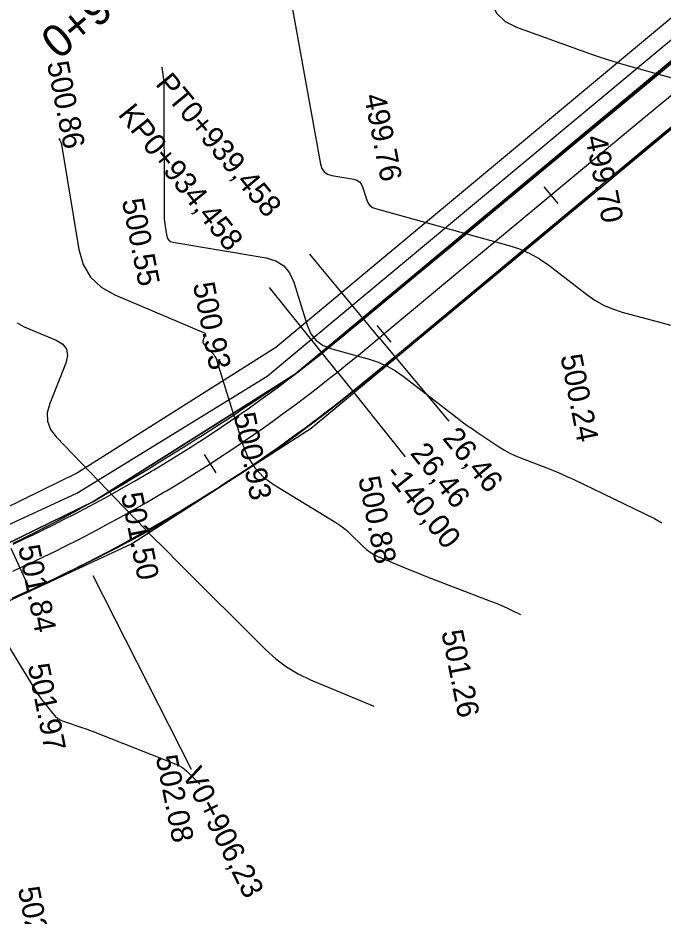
# Model space of a CAD drawing. Extents: x -636600 to -628587, y -1090963 to -1085869.
# Drawn here: x -629641.2 to -629581.8, y -1090525.3 to -1090442.6 of the extents above; entities that cross this region are included whole.
import ezdxf

# ---------------------------------------------------------------- set-up
doc = ezdxf.new("R2010")
doc.units = 0
for name, color, linetype in [('01_PARCELY_NÁVRH_PC', 7, 'Continuous'), ('06_ÚSES_IP_NAVRH', 7, 'Continuous'), ('Ex_Major Contours', 7, 'Continuous'), ('Ex_Minor Contours', 7, 'Continuous'), ('HEKTOMETRY100', 7, 'Continuous'), ('HEKTOMETRY20', 7, 'Continuous'), ('HL_BODY', 7, 'Continuous'), ('koty_vše', 7, 'Continuous'), ('POLOMERY', 7, 'Continuous'), ('situace_osa', 7, 'Continuous'), ('situace_těleso', 7, 'Continuous'), ('situace_vozovka', 7, 'Continuous'), ('VRCHOLY', 7, 'Continuous')]:
    doc.layers.add(name, color=color, linetype=linetype)

msp = doc.modelspace()

# ---------------------------------------------------------------- linework, layer by layer
at = {"layer": '01_PARCELY_NÁVRH_PC'}
for points in [[(-629847.268, -1090544.916), (-629662.104, -1090498.529), (-629646.495, -1090493.05), (-629634.26, -1090487.093), (-629615.686, -1090475.355), (-629557.933, -1090427.231), (-629554.65, -1090422.019), (-629539.331, -1090409.32), (-629533.536, -1090406.901), (-629497.762, -1090372.287), (-629488.059, -1090365.855), (-629480.703, -1090362.631), (-629491.445, -1090364.5), (-629499.65, -1090369.939), (-629535.214, -1090404.351), (-629617.455, -1090472.924), (-629635.723, -1090484.468), (-629647.652, -1090490.277), (-629662.967, -1090495.652), (-629847.268, -1090541.823)], [(-629497.762, -1090372.287), (-629533.536, -1090406.901), (-629539.331, -1090409.32), (-629554.65, -1090422.019), (-629557.933, -1090427.231), (-629615.686, -1090475.355), (-629634.26, -1090487.093), (-629646.495, -1090493.05), (-629662.104, -1090498.529), (-629847.268, -1090544.916)], [(-629847.268, -1090550.093), (-629665.921, -1090504.36), (-629648.758, -1090499.351), (-629630.773, -1090490.984), (-629614.22, -1090480.347), (-629531.575, -1090411.653)]]:
    msp.add_lwpolyline(points, dxfattribs=at)
at = {"layer": '06_ÚSES_IP_NAVRH'}
msp.add_lwpolyline([(-629847.268, -1090543.439), (-629818.166, -1090535.98), (-629661.354, -1090496.882), (-629647.184, -1090491.578), (-629635.801, -1090486.338), (-629618.25, -1090475.565), (-629536.227, -1090407.194), (-629498.949, -1090371.676), (-629491.149, -1090365.956)], dxfattribs=at)
at = {"layer": 'Ex_Major Contours'}
msp.add_lwpolyline([(-629616.176, -1090440.375), (-629613.365, -1090456.027), (-629613.241, -1090456.424), (-629613.025, -1090456.728), (-629612.718, -1090456.941), (-629612.321, -1090457.062), (-629610.292, -1090457.404), (-629610.005, -1090457.489), (-629609.772, -1090457.637), (-629609.595, -1090457.847), (-629609.473, -1090458.121), (-629609.093, -1090459.34), (-629608.972, -1090459.618), (-629608.797, -1090459.84), (-629608.569, -1090460.008), (-629608.288, -1090460.12), (-629595.993, -1090463.507), (-629595.009, -1090463.83), (-629594.069, -1090464.242), (-629593.174, -1090464.745), (-629592.324, -1090465.337), (-629588.824, -1090468.034), (-629588.071, -1090468.558), (-629587.278, -1090469.001), (-629586.445, -1090469.363), (-629585.572, -1090469.645), (-629582.001, -1090470.61), (-629581.109, -1090470.854)], dxfattribs=at)
at = {"layer": 'Ex_Minor Contours'}
for points in [[(-629607.555, -1090429.911), (-629606.862, -1090430.105), (-629600.866, -1090431.808), (-629599.793, -1090432.266), (-629598.998, -1090432.953), (-629598.483, -1090433.868), (-629598.246, -1090435.011), (-629597.859, -1090440.041), (-629597.626, -1090441.195), (-629597.121, -1090442.141), (-629596.343, -1090442.879), (-629595.292, -1090443.41), (-629589.333, -1090445.556), (-629588.034, -1090446.01), (-629586.727, -1090446.438), (-629585.412, -1090446.84), (-629584.089, -1090447.217), (-629578.781, -1090448.675)], [(-629627.956, -1090447.1), (-629627.795, -1090448.437), (-629627.75, -1090460.845), (-629627.745, -1090461.075), (-629627.729, -1090461.305), (-629627.703, -1090461.533), (-629627.667, -1090461.761), (-629627.504, -1090462.67), (-629627.44, -1090462.873), (-629627.329, -1090463.03), (-629627.171, -1090463.139), (-629626.967, -1090463.201), (-629618.359, -1090464.656), (-629617.466, -1090464.92), (-629616.743, -1090465.379), (-629616.192, -1090466.033), (-629615.811, -1090466.884), (-629614.573, -1090470.865), (-629614.233, -1090471.642), (-629613.743, -1090472.265), (-629613.104, -1090472.734), (-629612.316, -1090473.048), (-629608.866, -1090473.999), (-629608.023, -1090474.275), (-629607.218, -1090474.629), (-629606.451, -1090475.059), (-629605.723, -1090475.566), (-629600.749, -1090479.398), (-629600.29, -1090479.746), (-629599.824, -1090480.086), (-629599.353, -1090480.418), (-629598.876, -1090480.742), (-629596.958, -1090482.022), (-629596.471, -1090482.328), (-629595.97, -1090482.606), (-629595.454, -1090482.856), (-629594.923, -1090483.077), (-629592.427, -1090484.038), (-629591.834, -1090484.273), (-629591.247, -1090484.52), (-629590.664, -1090484.779), (-629590.086, -1090485.049), (-629582.575, -1090488.655), (-629581.907, -1090489.07)], [(-629637.447, -1090453.66), (-629637.349, -1090453.814), (-629637.266, -1090454.01), (-629637.214, -1090454.223), (-629635.602, -1090463.882), (-629635.209, -1090465.266), (-629634.528, -1090466.424), (-629633.56, -1090467.355), (-629632.304, -1090468.06), (-629624.118, -1090471.517), (-629624.032, -1090471.569), (-629623.983, -1090471.636), (-629623.97, -1090471.718), (-629623.993, -1090471.816), (-629624.161, -1090472.237), (-629624.187, -1090472.339), (-629624.184, -1090472.436), (-629624.151, -1090472.526), (-629624.087, -1090472.611), (-629623.331, -1090473.395), (-629623.19, -1090473.56), (-629623.071, -1090473.737), (-629622.973, -1090473.927), (-629622.897, -1090474.13), (-629620.49, -1090481.876), (-629620.032, -1090483.002), (-629619.4, -1090483.992), (-629618.593, -1090484.847), (-629617.613, -1090485.566), (-629611.923, -1090489.036), (-629611.573, -1090489.263), (-629611.238, -1090489.51), (-629610.918, -1090489.777), (-629610.614, -1090490.063), (-629609.428, -1090491.246), (-629609.12, -1090491.525), (-629608.789, -1090491.77), (-629608.437, -1090491.982), (-629608.061, -1090492.16), (-629605.646, -1090493.166), (-629605.114, -1090493.385), (-629604.581, -1090493.601), (-629604.046, -1090493.814), (-629603.509, -1090494.022), (-629597.677, -1090496.269), (-629597.175, -1090496.468), (-629596.677, -1090496.677), (-629596.183, -1090496.896), (-629595.693, -1090497.125), (-629594.916, -1090497.498)], [(-629641.294, -1090470.627), (-629640.635, -1090470.997), (-629637.696, -1090472.239), (-629637.09, -1090472.603), (-629636.741, -1090473.075), (-629636.649, -1090473.654), (-629636.815, -1090474.342), (-629638.297, -1090478.07), (-629638.517, -1090478.914), (-629638.49, -1090479.709), (-629638.214, -1090480.455), (-629637.69, -1090481.153), (-629631.458, -1090487.622), (-629630.2, -1090488.922), (-629628.935, -1090490.215), (-629627.664, -1090491.502), (-629626.386, -1090492.782), (-629618.408, -1090500.738), (-629617.472, -1090501.585), (-629616.469, -1090502.33), (-629615.397, -1090502.973), (-629614.256, -1090503.514), (-629608.443, -1090505.935)], [(-629643.142, -1090498.751), (-629639.605, -1090504.501), (-629639.426, -1090504.782), (-629639.239, -1090505.057), (-629639.044, -1090505.326), (-629638.841, -1090505.59), (-629638.011, -1090506.632), (-629637.791, -1090506.873), (-629637.543, -1090507.076), (-629637.268, -1090507.24), (-629636.966, -1090507.366), (-629635.327, -1090507.921), (-629634.95, -1090508.051), (-629634.574, -1090508.186), (-629634.2, -1090508.326), (-629633.828, -1090508.47), (-629626.662, -1090511.293), (-629626.388, -1090511.418), (-629626.131, -1090511.568), (-629625.89, -1090511.743), (-629625.667, -1090511.945), (-629624.628, -1090512.981), (-629624.497, -1090513.099), (-629624.464, -1090513.124)]]:
    msp.add_lwpolyline(points, dxfattribs=at)
at = {"layer": 'HEKTOMETRY100'}
msp.add_lwpolyline([(-629641.891, -1090491.394), (-629640.226, -1090495.031)], dxfattribs=at)
at = {"layer": 'HEKTOMETRY20'}
for points in [[(-629592.771, -1090458.112), (-629591.493, -1090459.65)], [(-629608.155, -1090470.892), (-629606.877, -1090472.431)], [(-629624.07, -1090482.78), (-629622.987, -1090484.461)]]:
    msp.add_lwpolyline(points, dxfattribs=at)
at = {"layer": 'HL_BODY'}
for points in [[(-629607.933, -1090472.007), (-629614.323, -1090464.316)], [(-629611.797, -1090475.18), (-629618.049, -1090467.375)]]:
    msp.add_lwpolyline(points, dxfattribs=at)
at = {"layer": 'POLOMERY'}
for points in [[(-629607.933, -1090472.007), (-629601.542, -1090479.699)], [(-629611.797, -1090475.18), (-629605.546, -1090482.984)]]:
    msp.add_lwpolyline(points, dxfattribs=at)
at = {"layer": 'situace_osa'}
msp.add_lwpolyline([(-629641.693, -1090493.501), (-629641.059, -1090493.213), (-629640.724, -1090493.059), (-629639.758, -1090492.609), (-629638.796, -1090492.153), (-629637.837, -1090491.688), (-629636.882, -1090491.217), (-629636.55, -1090491.051), (-629635.93, -1090490.738), (-629634.982, -1090490.252), (-629634.038, -1090489.759), (-629633.097, -1090489.258), (-629632.161, -1090488.751), (-629632.122, -1090488.73), (-629631.228, -1090488.236), (-629630.299, -1090487.715), (-629629.374, -1090487.186), (-629628.453, -1090486.65), (-629627.779, -1090486.252), (-629627.537, -1090486.107), (-629626.624, -1090485.558), (-629625.716, -1090485.001), (-629624.812, -1090484.437), (-629623.912, -1090483.867), (-629623.528, -1090483.621), (-629623.017, -1090483.29), (-629622.126, -1090482.706), (-629621.239, -1090482.115), (-629620.357, -1090481.517), (-629619.48, -1090480.913), (-629619.374, -1090480.839), (-629618.607, -1090480.302), (-629617.739, -1090479.685), (-629616.876, -1090479.061), (-629616.017, -1090478.43), (-629615.321, -1090477.911), (-629615.163, -1090477.793), (-629614.314, -1090477.149), (-629613.47, -1090476.499), (-629612.631, -1090475.842), (-629611.797, -1090475.18), (-629611.375, -1090474.84), (-629610.825, -1090474.394), (-629609.858, -1090473.602), (-629608.894, -1090472.806), (-629607.933, -1090472.007), (-629607.516, -1090471.661), (-629603.67, -1090468.466), (-629599.824, -1090465.271), (-629595.978, -1090462.076), (-629592.132, -1090458.881), (-629588.286, -1090455.686), (-629584.44, -1090452.491), (-629580.594, -1090449.296)], dxfattribs=at)
at = {"layer": 'situace_těleso'}
for points in [[(-629578.284, -1090444.252), (-629582.098, -1090447.486), (-629585.902, -1090450.731), (-629589.744, -1090453.931), (-629593.627, -1090457.082), (-629597.444, -1090460.312), (-629601.27, -1090463.53), (-629605.109, -1090466.734), (-629608.956, -1090469.928), (-629609.372, -1090470.274), (-629610.331, -1090471.073), (-629611.29, -1090471.863), (-629612.25, -1090472.643), (-629612.796, -1090473.08), (-629613.213, -1090473.412), (-629614.038, -1090474.058), (-629614.869, -1090474.698), (-629615.686, -1090475.355), (-629616.548, -1090475.952), (-629616.708, -1090476.062), (-629617.413, -1090476.544), (-629618.283, -1090477.129), (-629619.157, -1090477.707), (-629620.035, -1090478.279), (-629620.798, -1090478.791), (-629620.904, -1090478.862), (-629621.777, -1090479.438), (-629622.654, -1090480.009), (-629623.535, -1090480.573), (-629624.42, -1090481.13), (-629624.928, -1090481.446), (-629625.309, -1090481.682), (-629626.199, -1090482.231), (-629627.079, -1090482.796), (-629627.963, -1090483.354), (-629628.851, -1090483.907), (-629629.087, -1090484.052), (-629629.743, -1090484.453), (-629630.639, -1090484.993), (-629631.538, -1090485.527), (-629632.442, -1090486.055), (-629633.312, -1090486.556), (-629633.349, -1090486.577), (-629634.26, -1090487.093), (-629635.175, -1090487.602), (-629636.094, -1090488.104), (-629637.018, -1090488.596), (-629637.622, -1090488.914), (-629637.946, -1090489.082), (-629638.877, -1090489.561), (-629639.812, -1090490.032), (-629640.751, -1090490.497), (-629641.694, -1090490.955)], [(-629641.719, -1090496.076), (-629640.739, -1090495.614), (-629640.099, -1090495.308), (-629639.763, -1090495.145), (-629638.79, -1090494.669), (-629637.818, -1090494.193), (-629636.849, -1090493.71), (-629635.873, -1090493.242), (-629635.534, -1090493.077), (-629634.9, -1090492.767), (-629633.931, -1090492.284), (-629632.965, -1090491.793), (-629632.004, -1090491.296), (-629631.046, -1090490.79), (-629631.006, -1090490.769), (-629630.092, -1090490.276), (-629629.142, -1090489.756), (-629628.203, -1090489.217), (-629627.274, -1090488.659), (-629626.595, -1090488.244), (-629626.35, -1090488.094), (-629625.431, -1090487.521), (-629624.516, -1090486.942), (-629623.606, -1090486.355), (-629622.699, -1090485.764), (-629622.305, -1090485.521), (-629621.779, -1090485.193), (-629620.864, -1090484.615), (-629619.952, -1090484.03), (-629619.045, -1090483.439), (-629618.14, -1090482.842), (-629618.033, -1090482.766), (-629617.259, -1090482.213), (-629616.382, -1090481.577), (-629615.509, -1090480.936), (-629614.641, -1090480.289), (-629613.937, -1090479.757), (-629613.777, -1090479.635), (-629612.918, -1090478.976), (-629612.064, -1090478.311), (-629611.214, -1090477.64), (-629610.368, -1090476.964), (-629609.941, -1090476.618), (-629609.384, -1090476.164), (-629608.409, -1090475.362), (-629607.441, -1090474.559), (-629606.479, -1090473.758), (-629606.062, -1090473.411), (-629602.216, -1090470.217), (-629598.362, -1090467.031), (-629594.501, -1090463.854), (-629590.633, -1090460.686), (-629586.761, -1090457.522), (-629582.955, -1090454.278), (-629579.144, -1090451.042)]]:
    msp.add_lwpolyline(points, dxfattribs=at)
at = {"layer": 'situace_vozovka'}
for points in [[(-629641.666, -1090491.016), (-629640.716, -1090490.573), (-629639.769, -1090490.124), (-629638.825, -1090489.667), (-629637.885, -1090489.203), (-629637.559, -1090489.04), (-629636.949, -1090488.732), (-629636.016, -1090488.254), (-629635.087, -1090487.768), (-629634.162, -1090487.276), (-629633.24, -1090486.777), (-629633.202, -1090486.756), (-629632.322, -1090486.27), (-629631.408, -1090485.757), (-629630.498, -1090485.237), (-629629.592, -1090484.71), (-629628.929, -1090484.318), (-629628.69, -1090484.176), (-629627.793, -1090483.635), (-629626.899, -1090483.087), (-629626.009, -1090482.532), (-629625.124, -1090481.971), (-629624.746, -1090481.729), (-629624.243, -1090481.403), (-629623.366, -1090480.829), (-629622.494, -1090480.247), (-629621.626, -1090479.659), (-629620.763, -1090479.065), (-629620.658, -1090478.992), (-629619.904, -1090478.464), (-629619.05, -1090477.856), (-629618.201, -1090477.242), (-629617.356, -1090476.622), (-629616.671, -1090476.111), (-629616.516, -1090475.995), (-629615.681, -1090475.361), (-629614.85, -1090474.722), (-629614.025, -1090474.076), (-629613.204, -1090473.424), (-629612.788, -1090473.089), (-629612.245, -1090472.649), (-629611.288, -1090471.865), (-629610.33, -1090471.074), (-629609.37, -1090470.277), (-629608.954, -1090469.931), (-629605.108, -1090466.736), (-629601.262, -1090463.541), (-629597.416, -1090460.345), (-629593.57, -1090457.15), (-629589.724, -1090453.955), (-629585.878, -1090450.76), (-629582.032, -1090447.565), (-629578.186, -1090444.37)], [(-629641.755, -1090495.994), (-629640.767, -1090495.552), (-629640.122, -1090495.259), (-629639.782, -1090495.103), (-629638.801, -1090494.646), (-629637.823, -1090494.181), (-629636.849, -1090493.71), (-629635.878, -1090493.231), (-629635.541, -1090493.062), (-629634.911, -1090492.744), (-629633.948, -1090492.25), (-629632.989, -1090491.749), (-629632.033, -1090491.241), (-629631.081, -1090490.725), (-629631.042, -1090490.704), (-629630.133, -1090490.202), (-629629.19, -1090489.672), (-629628.25, -1090489.135), (-629627.314, -1090488.59), (-629626.63, -1090488.186), (-629626.383, -1090488.039), (-629625.456, -1090487.48), (-629624.533, -1090486.915), (-629623.614, -1090486.342), (-629622.7, -1090485.763), (-629622.31, -1090485.512), (-629621.79, -1090485.176), (-629620.885, -1090484.583), (-629619.984, -1090483.982), (-629619.088, -1090483.375), (-629618.197, -1090482.761), (-629618.089, -1090482.686), (-629617.31, -1090482.141), (-629616.428, -1090481.513), (-629615.551, -1090480.879), (-629614.678, -1090480.238), (-629613.971, -1090479.711), (-629613.811, -1090479.591), (-629612.948, -1090478.937), (-629612.091, -1090478.276), (-629611.238, -1090477.609), (-629610.391, -1090476.936), (-629609.962, -1090476.591), (-629609.405, -1090476.139), (-629608.428, -1090475.339), (-629607.458, -1090474.538), (-629606.495, -1090473.738), (-629606.078, -1090473.392), (-629602.232, -1090470.197), (-629598.386, -1090467.002), (-629594.54, -1090463.807), (-629590.694, -1090460.612), (-629586.849, -1090457.416), (-629583.003, -1090454.221), (-629579.157, -1090451.026)]]:
    msp.add_lwpolyline(points, dxfattribs=at)
at = {"layer": 'VRCHOLY'}
msp.add_lwpolyline([(-629634.312, -1090493.923), (-629625.256, -1090511.755)], dxfattribs=at)

# ---------------------------------------------------------------- texts
at = {"layer": 'HEKTOMETRY20'}
msp.add_text('0+940', height=3, rotation=39.71906, dxfattribs=at).set_placement((-629637.469, -1090446.493))
at = {"layer": 'HL_BODY'}
for s, rotation, p in [('PT0+939,458', 309.71906, (-629628.626, -1090448.663)), ('KP0+934,458', 308.69592, (-629632.071, -1090451.47))]:
    msp.add_text(s, height=2, rotation=rotation, dxfattribs=at).set_placement(p)
at = {"layer": 'koty_vše'}
for s, p in [('500.86', (-629638.56, -1090446.723)), ('499.76', (-629609.348, -1090449.728)), ('499.70', (-629588.967, -1090453.547)), ('500.55', (-629631.66, -1090459.368)), ('500.93', (-629625.115, -1090467.085)), ('500.24', (-629591.259, -1090473.716)), ('500.93', (-629621.36, -1090479.084)), ('500.88', (-629609.88, -1090484.951)), ('501.50', (-629631.737, -1090486.446)), ('501.84', (-629641.208, -1090491.276)), ('501.26', (-629602.221, -1090499.111)), ('501.97', (-629640.326, -1090502.206)), ('502.08', (-629628.534, -1090510.628)), ('502.43', (-629641.238, -1090522.756))]:
    msp.add_text(s, height=2, rotation=281.21136, dxfattribs=at).set_placement(p)
at = {"layer": 'POLOMERY'}
for s, rotation, p in [('26,46', 309.71906, (-629602.191, -1090481.294)), ('26,46', 308.69592, (-629605.155, -1090482.672)), ('-140,00', 308.69592, (-629607.497, -1090484.547))]:
    msp.add_text(s, height=2, rotation=rotation, dxfattribs=at).set_placement(p)
at = {"layer": 'VRCHOLY'}
msp.add_text('V0+906,23', height=2, rotation=296.92414, dxfattribs=at).set_placement((-629626.148, -1090512.208))

doc.saveas('drawing.dxf')
